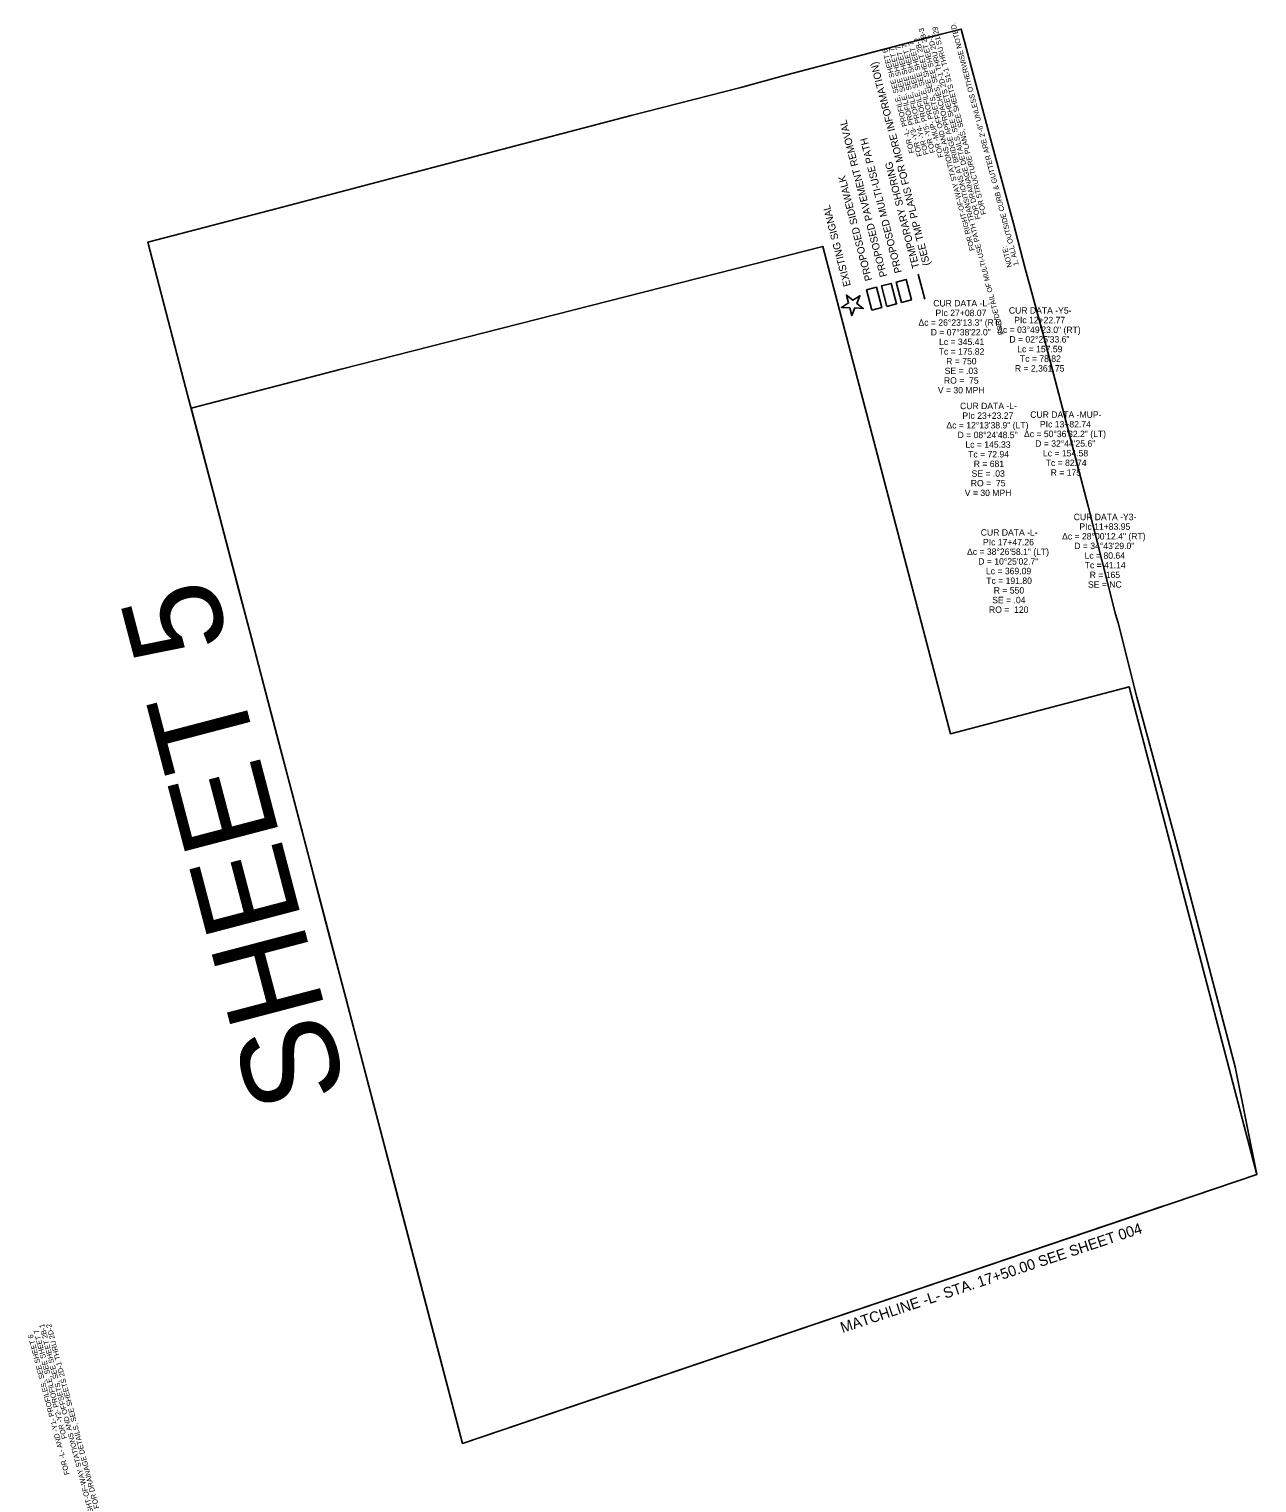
# Model space of a CAD drawing. Extents: x 1366798 to 1369150, y 878329 to 881399.
# Drawn here: x 1367719 to 1369150, y 879705 to 881399 of the extents above; entities that cross this region are included whole.
import ezdxf

# ---------------------------------------------------------------- set-up
doc = ezdxf.new("R2010")
doc.units = 0
for name, color, linetype in [('Matchline Text', 7, 'Continuous'), ('P_NCDOT_Horizontal_Alignment_Curve_and_Spiral_Data', 7, 'Continuous'), ('P_NCDOT_Horizontal_Alignment_Direction_Label', 7, 'Continuous'), ('P_NCDOT_Horizontal_Alignment_Station_Label', 7, 'Continuous'), ('P_NCDOT_Horizontal_Alignment_Station_Major_Label', 7, 'Continuous'), ('P_NCDOT_Horizontal_Alignment_Tick_Large', 7, 'Continuous'), ('P_NCDOT_Horizontal_Alignment_Tick_Small', 7, 'Continuous'), ('Prop Conc Curb and Gutter', 7, 'Continuous'), ('Prop Dimension', 7, 'Continuous'), ('Prop Horizontal Alignment Station Label', 7, 'Continuous'), ('Prop Lane Arrow CELL', 7, 'Continuous'), ('Prop Superelevation  Arrow CELL', 7, 'Continuous'), ('Prop Superelevation Label', 7, 'Continuous')]:
    doc.layers.add(name, color=color, linetype=linetype)

msp = doc.modelspace()

# ---------------------------------------------------------------- linework, layer by layer
at = {"layer": 'Matchline Text'}
msp.add_lwpolyline([(1368701.5, 881071.6), (1368695.2, 881095.4), (1368706.7, 881098.4), (1368713, 881074.6)], close=True, dxfattribs=at)
at = {"layer": 'P_NCDOT_Horizontal_Alignment_Curve_and_Spiral_Data'}
msp.add_line((1368763.1, 881084.3), (1368755.4, 881113.7), dxfattribs=at)
at = {"layer": 'P_NCDOT_Horizontal_Alignment_Direction_Label'}
msp.add_lwpolyline([(1368675.7, 881074.5), (1368678, 881065.4), (1368681.6, 881074.2), (1368691.3, 881073.7), (1368683.8, 881079.6), (1368687.4, 881088.4), (1368679.2, 881083.3), (1368671.8, 881089.2), (1368674.2, 881080.1), (1368666, 881074.9), (1368675.7, 881074.5)], dxfattribs=at)
at = {"layer": 'P_NCDOT_Horizontal_Alignment_Station_Label'}
msp.add_line((1368640.7, 879892), (1369041.5, 880027.7), dxfattribs=at)
at = {"layer": 'P_NCDOT_Horizontal_Alignment_Station_Major_Label'}
msp.add_lwpolyline([(1368736.1, 881080.6), (1368729.8, 881104.4), (1368741.3, 881107.5), (1368747.5, 881083.6)], close=True, dxfattribs=at)
at = {"layer": 'P_NCDOT_Horizontal_Alignment_Tick_Small'}
msp.add_lwpolyline([(1367916.6, 880925.1), (1368224.3, 879751), (1369150.2, 880064.5), (1369001.3, 880632.6), (1368792.9, 880578), (1368644.1, 881145.9), (1368083, 881002.8), (1368027.6, 880988.6), (1367908.1, 880957.3)], close=True, dxfattribs=at)
at = {"layer": 'Prop Dimension'}
msp.add_lwpolyline([(1368331.9, 879787.4), (1369150.2, 880064.5), (1369124.7, 880189.7), (1369056.3, 880450.3), (1369010.3, 880620.6), (1368988.3, 880707.1), (1368985.5, 880717.3), (1368953.6, 880843.2), (1368923.7, 880957.4), (1368900.1, 881046.3), (1368880.2, 881120.4), (1368866.6, 881172.7), (1368842.2, 881261.4), (1368826.1, 881322.4), (1368805.6, 881399.3), (1368782.3, 881393.2), (1368683.5, 881367.3), (1368602.4, 881346), (1368548.5, 881331.3), (1368420.8, 881298.4), (1368191.1, 881238.2), (1368008.1, 881190.3), (1367857.4, 881150.8), (1367899.7, 880989.4), (1367939.1, 880839), (1367963.8, 880745), (1367978.2, 880689.9), (1367997.5, 880616.4), (1368012.2, 880560.2), (1368025.7, 880508.6), (1368039, 880458.1), (1368051.9, 880408.7), (1368070.2, 880338.7), (1368088.6, 880268.7), (1368110.8, 880183.8), (1368131.5, 880105), (1368144.8, 880054.3), (1368165.4, 879975.7), (1368190.6, 879879.5), (1368224.3, 879751), (1368331.9, 879787.4), (1368331.9, 879787.4)], close=True, dxfattribs=at)
at = {"layer": 'Prop Horizontal Alignment Station Label'}
msp.add_lwpolyline([(1368736.1, 881080.6), (1368729.8, 881104.4), (1368741.3, 881107.5), (1368747.5, 881083.6)], close=True, dxfattribs=at)
at = {"layer": 'Prop Lane Arrow CELL'}
msp.add_lwpolyline([(1368718.8, 881076.1), (1368712.5, 881099.9), (1368724, 881102.9), (1368730.3, 881079.1)], close=True, dxfattribs=at)

# ---------------------------------------------------------------- texts
at = {"layer": 'P_NCDOT_Horizontal_Alignment_Tick_Large'}
for s, p in [('CUR DATA -L-', (1368772.9, 881076)), ('CUR DATA -Y5-', (1368861.1, 881067.6)), ('Δc = 26°23\'13.3" (RT)', (1368755.7, 881053.5)), ('PIc 27+08.07', (1368775.5, 881064.7)), ('PIc 12+22.77', (1368867.3, 881056.4)), ('D = 07°38\'22.0"', (1368770, 881042.2)), ('Δc = 03°49\'23.0" (RT)', (1368847.5, 881045.1)), ('D = 02°25\'33.6"', (1368861.7, 881033.9)), ('Tc = 175.82', (1368779.3, 881019.7)), ('Lc = 345.41', (1368779.7, 881031)), ('Lc = 157.59', (1368870.8, 881022.6)), ('R = 750', (1368788, 881008.5)), ('R = 2,361.75', (1368868.1, 881000.1)), ('Tc = 78.82', (1368874, 881011.4)), ('RO =  75', (1368785.4, 880986)), ('SE = .03', (1368786.3, 880997.2)), ('V = 30 MPH', (1368778.3, 880974.7)), ('CUR DATA -L-', (1368804.2, 880956.3)), ('Δc = 12°13\'38.9" (LT)', (1368788.3, 880933.8)), ('PIc 23+23.27', (1368806.9, 880945)), ('CUR DATA -MUP-', (1368886, 880946.2)), ('PIc 13+82.74', (1368897.3, 880935)), ('D = 08°24\'48.5"', (1368801.3, 880922.5)), ('Δc = 50°36\'32.2" (LT)', (1368878.7, 880923.7)), ('Lc = 145.33', (1368810.4, 880911.3)), ('Tc = 72.94', (1368813.6, 880900)), ('D = 32°44\'25.6"', (1368891.8, 880912.5)), ('Lc = 154.58', (1368900.8, 880901.2)), ('R = 681', (1368820.1, 880888.8)), ('Tc = 82.74', (1368904, 880890)), ('RO =  75', (1368816.7, 880866.3)), ('SE = .03', (1368817.6, 880877.5)), ('R = 175', (1368909.8, 880878.7)), ('V = 30 MPH', (1368809.7, 880855)), ('CUR DATA -Y3-', (1368936.7, 880826.9)), ('PIc 11+83.95', (1368943.2, 880815.7)), ('CUR DATA -L-', (1368828.3, 880808.9)), ('PIc 17+47.26', (1368830.9, 880797.6)), ('Δc = 28°00\'12.4" (RT)', (1368923.1, 880804.4)), ('Δc = 38°26\'58.1" (LT)', (1368812.3, 880786.4)), ('D = 34°43\'29.0"', (1368937.3, 880793.2)), ('Lc = 80.64', (1368949.3, 880781.9)), ('D = 10°25\'02.7"', (1368825.4, 880775.1)), ('Lc = 369.09', (1368834.4, 880763.9)), ('Tc = 41.14', (1368949.5, 880770.7)), ('Tc = 191.80', (1368834.7, 880752.6)), ('SE = NC', (1368953.3, 880748.2)), ('R = 165', (1368955.3, 880759.4)), ('SE = .04', (1368841.7, 880730.1)), ('R = 550', (1368843.5, 880741.4)), ('RO =  120', (1368837.9, 880718.9))]:
    msp.add_text(s, height=7.5, dxfattribs=at).set_placement(p)
at = {"layer": 'Prop Conc Curb and Gutter'}
msp.add_text('MATCHLINE -L- STA. 17+50.00 SEE SHEET 004', height=12.5, rotation=18.4634, dxfattribs=at).set_placement((1368667.2, 879879.5))
at = {"layer": 'Prop Dimension'}
msp.add_text('SHEET 5', height=112.11, rotation=104.6851, dxfattribs=at).set_placement((1368090.3, 880159.4))
at = {"layer": 'Prop Superelevation  Arrow CELL'}
for s, p in [('1. ALL OUTSIDE CURB & GUTTER ARE 2\'-6" UNLESS OTHERWISE NOTED.', (1368872.7, 881124.4)), ('FOR RIGHT-OF-WAY STATIONS AND OFFSETS, SEE SHEET 2B-2', (1368821.4, 881141.7)), ('FOR DETAIL OF MULTI-USE PATH TRANSITIONS AT BRIDGE APPROACHES, SEE SHEET 2B-3', (1368855.2, 881043.6)), ('FOR DRAINAGE DETAILS, SEE SHEETS 2D-1 THRU 2D-2', (1368828.1, 881178.3)), ('FOR STRUCTURE PLANS, SEE SHEETS S1-1 THRU S1-29', (1368834.8, 881183.7)), ('FOR -L- PROFILE, SEE SHEET 6', (1368751, 881255.2)), ('FOR -Y3- PROFILE, SEE SHEET 7', (1368760.1, 881251.5)), ('FOR -Y4- PROFILE, SEE SHEET 7', (1368767.7, 881253.5)), ('FOR -Y5- PROFILE, SEE SHEET 7', (1368775.3, 881255.5)), ('FOR -MUP- PROFILE, SEE SHEET 7', (1368784.8, 881250.3)), ('NOTE:', (1368865.1, 881122.4)), ('FOR -L- AND -Y1- PROFILES, SEE SHEET 6', (1367766.3, 879715.1)), ('FOR -Y2- PROFILE, SEE SHEET 7', (1367763.4, 879757)), ('FOR RIGHT-OF-WAY STATIONS AND OFFSETS, SEE SHEET 2B-1', (1367801.5, 879642.9)), ('FOR DRAINAGE DETAILS, SEE SHEETS 2D-1 THRU 2D-2', (1367801, 879675.8))]:
    msp.add_text(s, height=6, rotation=104.6851, dxfattribs=at).set_placement(p)
at = {"layer": 'Prop Superelevation Label'}
for s, p in [('(SEE TMP PLANS FOR MORE INFORMATION)', (1368769.4, 881124.7)), ('PROPOSED PAVEMENT REMOVAL', (1368719.3, 881111.5)), ('PROPOSED MULTI-USE PATH', (1368736.6, 881116.1)), ('PROPOSED SIDEWALK', (1368702, 881107)), ('TEMPORARY SHORING', (1368757, 881121.4)), ('EXISTING SIGNAL', (1368676.9, 881100.4))]:
    msp.add_text(s, height=8.5, rotation=104.5986, dxfattribs=at).set_placement(p)

doc.saveas('drawing.dxf')
